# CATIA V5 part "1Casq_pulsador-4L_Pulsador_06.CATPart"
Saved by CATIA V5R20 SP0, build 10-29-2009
Part number: 1Casq_pulsador-4L_Pulsador_06
Revision: ANY
Definition: UNKNOWN
Nomenclature: 1Casq_pulsador-4L_Pulsador_06
Source: Unknown
Bounding box of the stored display mesh (mm): x -5.8 to 5.8, y 0 to 15.3, z -5.8 to 5.8
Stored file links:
  C:\Users\Utente\Desktop\IO LAVORO\3D X SITO CF\CUMSA\3D files BE\BE 041216\1Casq_pulsador-4L_Pulsador_06.CATPart
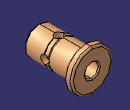
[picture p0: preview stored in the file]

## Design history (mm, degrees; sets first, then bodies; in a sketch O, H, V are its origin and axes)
Body1 "MatrizC1" (main body)
  Solid1: solid without history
